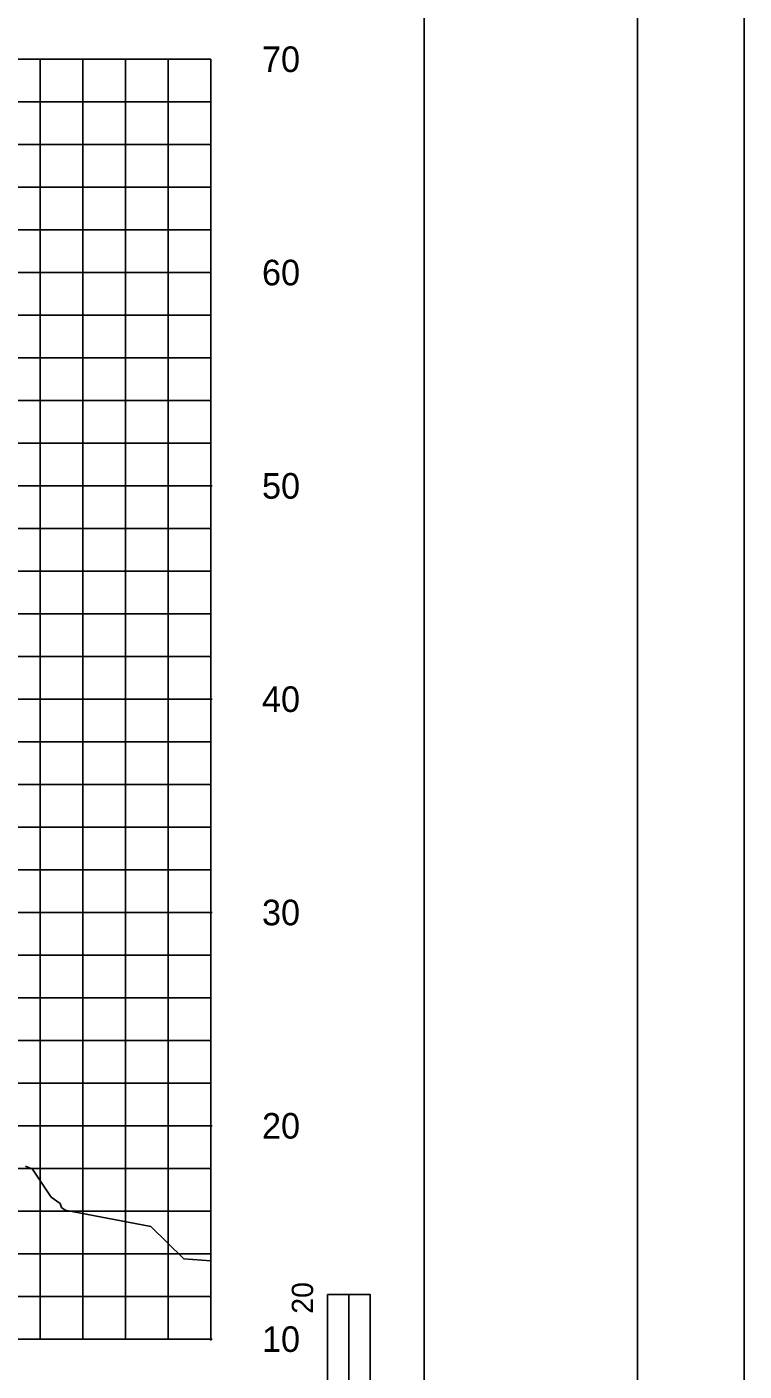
# Model space of a CAD drawing. Extents: x 1797809 to 2198143, y 249608 to 1237864.
# Drawn here: x 2194819.1 to 2194852.7, y 1237161.6 to 1237224.6 of the extents above; entities that cross this region are included whole.
import ezdxf

# ---------------------------------------------------------------- set-up
doc = ezdxf.new("R2010")
doc.units = 0
for name, color, linetype in [('29', 7, 'Continuous'), ('31', 7, 'Continuous'), ('60', 7, 'Continuous'), ('DESIGN - SHEET - Light Grid', 7, 'Continuous'), ('GSCOLORFILL', 7, 'Continuous'), ('GSSHT', 7, 'Continuous'), ('Level 45', 7, 'Continuous')]:
    doc.layers.add(name, color=color, linetype=linetype)

msp = doc.modelspace()

# ---------------------------------------------------------------- linework, layer by layer
at = {"layer": '29'}
for p, q in [((2194833.16, 1237165.195), (2194833.16, 1237135.195)), ((2194835.16, 1237165.195), (2194833.16, 1237165.195)), ((2194833.16, 1237165.195), (2194833.16, 1237135.195)), ((2194835.16, 1237165.195), (2194833.16, 1237165.195)), ((2194835.16, 1237165.195), (2194835.16, 1237155.195)), ((2194835.16, 1237165.195), (2194835.16, 1237135.195)), ((2194835.16, 1237165.195), (2194835.16, 1237155.195)), ((2194835.16, 1237165.195), (2194835.16, 1237135.195))]:
    msp.add_line(p, q, dxfattribs=at)
msp.add_lwpolyline([(2194834.16, 1237155.195), (2194834.16, 1237165.195), (2194835.16, 1237165.195), (2194835.16, 1237155.195)], close=True, dxfattribs=at)
msp.add_lwpolyline([(2194834.16, 1237155.195), (2194834.16, 1237165.195), (2194835.16, 1237165.195), (2194835.16, 1237155.195)], close=True, dxfattribs=at)
at = {"layer": '60'}
for p, q in [((2194827.688, 1237163.106), (2194827.688, 1237223.106)), ((2194827.748, 1237203.106), (2194827.688, 1237203.106)), ((2194827.748, 1237193.106), (2194827.688, 1237193.106)), ((2194827.748, 1237183.106), (2194827.688, 1237183.106)), ((2194827.748, 1237173.106), (2194827.688, 1237173.106)), ((2194697.688, 1237163.106), (2194827.688, 1237163.106)), ((2194827.688, 1237163.046), (2194827.688, 1237163.106)), ((2194827.748, 1237163.106), (2194827.688, 1237163.106))]:
    msp.add_line(p, q, dxfattribs=at)
at = {"layer": 'DESIGN - SHEET - Light Grid'}
msp.add_lwpolyline([(2194819, 1237171.207), (2194819.326, 1237171.074), (2194820.2, 1237169.762), (2194820.627, 1237169.461), (2194820.696, 1237169.277), (2194820.853, 1237169.156), (2194824.872, 1237168.387), (2194826.423, 1237166.871), (2194827.688, 1237166.778)], dxfattribs=at)
at = {"layer": 'GSCOLORFILL'}
msp.add_lwpolyline([(2194525.191, 1237123.036), (2194847.691, 1237123.036), (2194847.691, 1237333.036), (2194525.191, 1237333.036)], close=True, dxfattribs=at)
at = {"layer": 'GSSHT'}
for p, q in [((2194697.688, 1237223.106), (2194827.688, 1237223.106)), ((2194819.688, 1237163.106), (2194819.688, 1237223.106)), ((2194821.688, 1237163.106), (2194821.688, 1237223.106)), ((2194823.688, 1237163.106), (2194823.688, 1237223.106)), ((2194825.688, 1237163.106), (2194825.688, 1237223.106)), ((2194827.688, 1237163.106), (2194827.688, 1237223.106)), ((2194697.688, 1237221.106), (2194827.688, 1237221.106)), ((2194697.688, 1237219.106), (2194827.688, 1237219.106)), ((2194697.688, 1237217.106), (2194827.688, 1237217.106)), ((2194697.688, 1237215.106), (2194827.688, 1237215.106)), ((2194697.688, 1237213.106), (2194827.688, 1237213.106)), ((2194697.688, 1237211.106), (2194827.688, 1237211.106)), ((2194697.688, 1237209.106), (2194827.688, 1237209.106)), ((2194697.688, 1237207.106), (2194827.688, 1237207.106)), ((2194697.688, 1237205.106), (2194827.688, 1237205.106)), ((2194697.688, 1237203.106), (2194827.688, 1237203.106)), ((2194697.688, 1237201.106), (2194827.688, 1237201.106)), ((2194697.688, 1237199.106), (2194827.688, 1237199.106)), ((2194697.688, 1237197.106), (2194827.688, 1237197.106)), ((2194697.688, 1237195.106), (2194827.688, 1237195.106)), ((2194697.688, 1237193.106), (2194827.688, 1237193.106)), ((2194697.688, 1237191.106), (2194827.688, 1237191.106)), ((2194697.688, 1237189.106), (2194827.688, 1237189.106)), ((2194697.688, 1237187.106), (2194827.688, 1237187.106)), ((2194697.688, 1237185.106), (2194827.688, 1237185.106)), ((2194697.688, 1237183.106), (2194827.688, 1237183.106)), ((2194697.688, 1237181.106), (2194827.688, 1237181.106)), ((2194697.688, 1237179.106), (2194827.688, 1237179.106)), ((2194697.688, 1237177.106), (2194827.688, 1237177.106)), ((2194697.688, 1237175.106), (2194827.688, 1237175.106)), ((2194697.688, 1237173.106), (2194827.688, 1237173.106)), ((2194697.688, 1237171.106), (2194827.688, 1237171.106)), ((2194697.688, 1237169.106), (2194827.688, 1237169.106)), ((2194697.688, 1237167.106), (2194827.688, 1237167.106)), ((2194697.688, 1237165.106), (2194827.688, 1237165.106)), ((2194697.688, 1237163.106), (2194827.688, 1237163.106))]:
    msp.add_line(p, q, dxfattribs=at)
msp.add_lwpolyline([(2194512.691, 1237118.036), (2194852.691, 1237118.036), (2194852.691, 1237338.036), (2194512.691, 1237338.036)], close=True, dxfattribs=at)
at = {"layer": 'Level 45'}
msp.add_lwpolyline([(2194537.688, 1237133.046), (2194837.688, 1237133.046), (2194837.688, 1237323.046), (2194537.688, 1237323.046)], close=True, dxfattribs=at)

# ---------------------------------------------------------------- texts
at = {"layer": '29'}
msp.add_text('20', height=0.9991, rotation=90.0572, dxfattribs=at).set_placement((2194832.485, 1237164.295))
msp.add_text('20', height=0.9991, rotation=90.0572, dxfattribs=at).set_placement((2194832.485, 1237164.295))
at = {"layer": '31'}
for s, p in [('70', (2194830.088, 1237222.506)), ('60', (2194830.088, 1237212.506)), ('50', (2194830.088, 1237202.506)), ('40', (2194830.088, 1237192.506)), ('30', (2194830.088, 1237182.506)), ('20', (2194830.088, 1237172.506)), ('10', (2194830.088, 1237162.506))]:
    msp.add_text(s, height=1.2, dxfattribs=at).set_placement(p)

doc.saveas('drawing.dxf')
